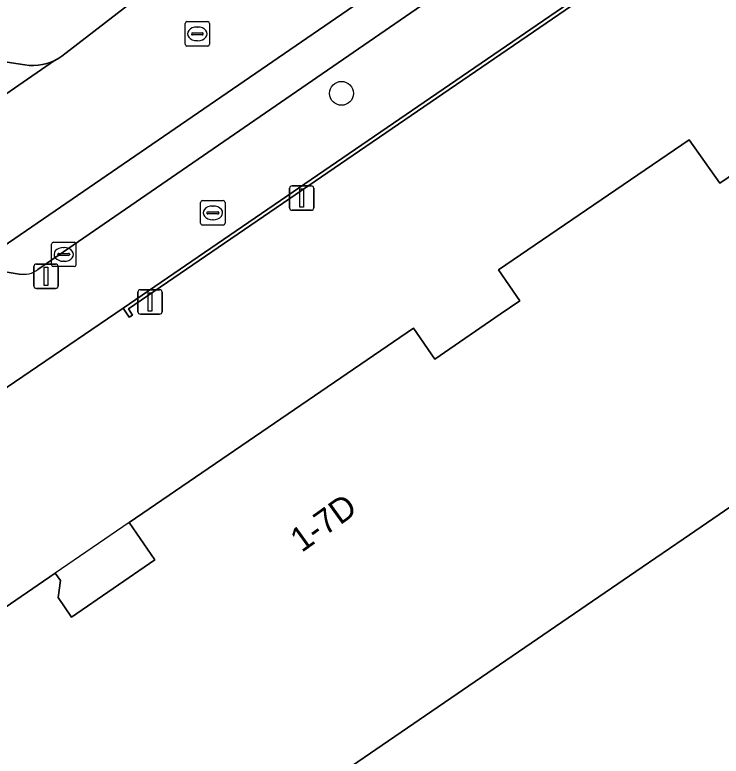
# Model space of a CAD drawing. Extents: x 157445 to 158888, y 383061 to 384688.
# Drawn here: x 158211.1 to 158240.06, y 383581.29 to 383611.7 of the extents above; entities that cross this region are included whole.
import ezdxf

# ---------------------------------------------------------------- set-up
doc = ezdxf.new("R2010")
doc.units = 0
for name, color, linetype in [('IMGEO_Boom', 7, 'Continuous'), ('IMGEO_Brandkraan', 7, 'Continuous'), ('IMGEO_Erf', 7, 'Continuous'), ('IMGEO_Kolk', 7, 'Continuous'), ('IMGEO_Lichtmast', 7, 'Continuous'), ('IMGEO_Muur', 7, 'Continuous'), ('IMGEO_Pand', 7, 'Continuous'), ('IMGEO_Pand_nummerreeks', 7, 'Continuous'), ('IMGEO_Pand_overbouw', 7, 'Continuous'), ('IMGEO_Parkeervlak_open', 7, 'Continuous'), ('IMGEO_Rijbaan_lokaal_open', 7, 'Continuous'), ('IMGEO_Rioolput', 7, 'Continuous'), ('IMGEO_Voetpad_open', 7, 'Continuous')]:
    doc.layers.add(name, color=color, linetype=linetype)

msp = doc.modelspace()

# ---------------------------------------------------------------- linework, layer by layer
at = {"layer": 'IMGEO_Boom'}
msp.add_circle((158224.494, 383608.475), 0.489, dxfattribs=at)
at = {"layer": 'IMGEO_Brandkraan'}
for p, q in [((158218.718, 383603.147), (158218.718, 383603.999)), ((158218.793, 383604.073), (158219.645, 383604.073)), ((158219.719, 383603.999), (158219.719, 383603.147)), ((158218.977, 383603.567), (158218.977, 383603.579)), ((158219.02, 383603.616), (158219.418, 383603.616)), ((158219.206, 383603.853), (158219.231, 383603.853)), ((158219.461, 383603.579), (158219.461, 383603.567)), ((158219.415, 383603.53), (158219.017, 383603.53)), ((158219.229, 383603.293), (158219.204, 383603.293)), ((158219.645, 383603.073), (158218.793, 383603.073))]:
    msp.add_line(p, q, dxfattribs=at)
for points in [[(158218.718, 383603.147), (158218.718, 383603.999)], [(158218.793, 383604.073), (158219.645, 383604.073)], [(158219.719, 383603.999), (158219.719, 383603.147)], [(158219.645, 383603.073), (158218.793, 383603.073)]]:
    msp.add_lwpolyline(points, dxfattribs=at)
for centre, radius, start, end in [((158218.795, 383603.997), 0.0765, 91.552, 178.448), ((158218.795, 383603.997), 0.0765, 91.552, 178.448), ((158219.643, 383603.997), 0.0765, 1.552, 88.448), ((158219.643, 383603.997), 0.0765, 1.552, 88.448), ((158219.017, 383603.576), 0.0403, 85.8775, 175.7526), ((158219.014, 383603.566), 0.0366, 178.938, 274.7102), ((158219.418, 383603.573), 0.043, 264.8664, 352.4533), ((158219.422, 383603.578), 0.0386, 1.7309, 96.639), ((158218.795, 383603.149), 0.0765, 181.552, 268.448), ((158218.795, 383603.149), 0.0765, 181.552, 268.448), ((158219.643, 383603.149), 0.0765, 271.552, 358.448), ((158219.643, 383603.149), 0.0765, 271.552, 358.448)]:
    msp.add_arc(centre, radius, start, end, dxfattribs=at)
for centre, major_axis, ratio, start_param, end_param in [((158219.205, 383603.573), (-0.387, 0.002), 0.722429, 4.712389, 7.853982), ((158219.23, 383603.573), (-0.39, 0.002), 0.717154, 1.570796, 4.712389)]:
    msp.add_ellipse(centre, major_axis=major_axis, ratio=ratio, start_param=start_param, end_param=end_param, dxfattribs=at)
at = {"layer": 'IMGEO_Erf'}
for points in [[(158240.122, 383614.615), (158240.015, 383614.801), (158239.881, 383614.717), (158239.2, 383615.691), (158215.763, 383599.631), (158215.929, 383599.377), (158215.792, 383599.296), (158215.538, 383599.669), (158207.907, 383594.462), (158208.164, 383594.074), (158208.035, 383593.982), (158207.86, 383594.239), (158192.558, 383583.752), (158193.231, 383582.756), (158193.094, 383582.665), (158193.198, 383582.481), (158193.29, 383582.542), (158193.385, 383582.412), (158192.146, 383581.575), (158209.881, 383555.629)], [(158200.748, 383580.567), (158212.758, 383588.789), (158212.978, 383588.491), (158212.869, 383587.792), (158213.429, 383586.988), (158216.843, 383589.337), (158215.793, 383590.872), (158227.446, 383598.845), (158228.316, 383597.574), (158231.001, 383599.411), (158231.8, 383599.958), (158230.932, 383601.23), (158238.75, 383606.566), (158240, 383604.79), (158243.968, 383607.489), (158249.07, 383600.072), (158246.747, 383598.511), (158248.015, 383596.714), (158238.501, 383590.195), (158236.822, 383589.045), (158223.385, 383579.839)]]:
    msp.add_lwpolyline(points, dxfattribs=at)
at = {"layer": 'IMGEO_Kolk'}
for p, q in [((158212.681, 383602.367), (158213.533, 383602.367)), ((158212.606, 383601.441), (158212.606, 383602.293)), ((158213.094, 383602.147), (158213.119, 383602.147)), ((158213.607, 383602.293), (158213.607, 383601.441)), ((158212.865, 383601.861), (158212.865, 383601.873)), ((158213.303, 383601.824), (158212.905, 383601.824)), ((158212.908, 383601.91), (158213.306, 383601.91)), ((158213.349, 383601.873), (158213.349, 383601.861)), ((158213.117, 383601.587), (158213.092, 383601.587)), ((158213.533, 383601.367), (158212.681, 383601.367))]:
    msp.add_line(p, q, dxfattribs=at)
for points in [[(158212.681, 383602.367), (158213.533, 383602.367)], [(158212.606, 383601.441), (158212.606, 383602.293)], [(158213.607, 383602.293), (158213.607, 383601.441)], [(158213.533, 383601.367), (158212.681, 383601.367)]]:
    msp.add_lwpolyline(points, dxfattribs=at)
for centre, radius, start, end in [((158212.683, 383602.291), 0.0765, 91.552, 178.448), ((158212.683, 383602.291), 0.0765, 91.552, 178.448), ((158213.531, 383602.291), 0.0765, 1.552, 88.448), ((158213.531, 383602.291), 0.0765, 1.552, 88.448), ((158212.905, 383601.87), 0.0403, 85.8775, 175.7526), ((158212.902, 383601.86), 0.0366, 178.938, 274.7102), ((158213.306, 383601.867), 0.043, 264.8664, 352.4533), ((158213.31, 383601.872), 0.0386, 1.7309, 96.639), ((158212.683, 383601.443), 0.0765, 181.552, 268.448), ((158212.683, 383601.443), 0.0765, 181.552, 268.448), ((158213.531, 383601.443), 0.0765, 271.552, 358.448), ((158213.531, 383601.443), 0.0765, 271.552, 358.448)]:
    msp.add_arc(centre, radius, start, end, dxfattribs=at)
for centre, major_axis, ratio, start_param, end_param in [((158213.093, 383601.867), (-0.387, 0.002), 0.722429, 4.712389, 7.853982), ((158213.118, 383601.867), (-0.39, 0.002), 0.717154, 1.570796, 4.712389)]:
    msp.add_ellipse(centre, major_axis=major_axis, ratio=ratio, start_param=start_param, end_param=end_param, dxfattribs=at)
at = {"layer": 'IMGEO_Lichtmast'}
for p, q in [((158222.365, 383603.78), (158222.365, 383604.58)), ((158222.365, 383604.58), (158222.365, 383603.78)), ((158222.465, 383604.68), (158223.255, 383604.68)), ((158223.255, 383604.68), (158222.465, 383604.68)), ((158223.355, 383604.58), (158223.355, 383603.78)), ((158223.355, 383603.78), (158223.355, 383604.58)), ((158223.255, 383603.68), (158222.465, 383603.68)), ((158222.465, 383603.68), (158223.255, 383603.68)), ((158211.982, 383601.472), (158212.772, 383601.472)), ((158212.772, 383601.472), (158211.982, 383601.472)), ((158211.882, 383600.572), (158211.882, 383601.372)), ((158211.882, 383601.372), (158211.882, 383600.572)), ((158212.872, 383601.372), (158212.872, 383600.572)), ((158212.872, 383600.572), (158212.872, 383601.372)), ((158212.772, 383600.472), (158211.982, 383600.472)), ((158211.982, 383600.472), (158212.772, 383600.472)), ((158216.146, 383599.518), (158216.146, 383600.318)), ((158216.146, 383600.318), (158216.146, 383599.518)), ((158216.246, 383600.418), (158217.036, 383600.418)), ((158217.036, 383600.418), (158216.246, 383600.418)), ((158217.136, 383600.318), (158217.136, 383599.518)), ((158217.136, 383599.518), (158217.136, 383600.318)), ((158217.036, 383599.418), (158216.246, 383599.418)), ((158216.246, 383599.418), (158217.036, 383599.418))]:
    msp.add_line(p, q, dxfattribs=at)
for points in [[(158222.785, 383604.555), (158222.935, 383604.555), (158222.935, 383603.805), (158222.785, 383603.805), (158222.785, 383604.555)], [(158212.302, 383601.347), (158212.452, 383601.347), (158212.452, 383600.597), (158212.302, 383600.597), (158212.302, 383601.347)], [(158216.566, 383600.293), (158216.716, 383600.293), (158216.716, 383599.543), (158216.566, 383599.543), (158216.566, 383600.293)]]:
    msp.add_lwpolyline(points, dxfattribs=at)
for centre, start, end in [((158222.465, 383604.58), 90, 180), ((158222.465, 383604.58), 90, 180), ((158223.255, 383604.58), 0, 90), ((158223.255, 383604.58), 360, 90), ((158222.465, 383603.78), 180, 270), ((158222.465, 383603.78), 180, 270), ((158223.255, 383603.78), 270, 0), ((158223.255, 383603.78), 270, 0), ((158211.982, 383601.372), 90, 180), ((158211.982, 383601.372), 90, 180), ((158212.772, 383601.372), 0, 90), ((158212.772, 383601.372), 360, 90), ((158211.982, 383600.572), 180, 270), ((158211.982, 383600.572), 180, 270), ((158212.772, 383600.572), 270, 0), ((158212.772, 383600.572), 270, 0), ((158216.246, 383600.318), 90, 180), ((158216.246, 383600.318), 90, 180), ((158217.036, 383600.318), 0, 90), ((158217.036, 383600.318), 360, 90), ((158216.246, 383599.518), 180, 270), ((158216.246, 383599.518), 180, 270), ((158217.036, 383599.518), 270, 0), ((158217.036, 383599.518), 270, 0)]:
    msp.add_arc(centre, 0.1, start, end, dxfattribs=at)
at = {"layer": 'IMGEO_Muur'}
msp.add_lwpolyline([(158239.233, 383615.894), (158215.538, 383599.669), (158215.792, 383599.296), (158215.929, 383599.377), (158215.763, 383599.631), (158239.2, 383615.691), (158239.881, 383614.717), (158240.015, 383614.801)], close=True, dxfattribs=at)
at = {"layer": 'IMGEO_Pand'}
msp.add_lwpolyline([(158223.385, 383579.839), (158236.822, 383589.045), (158238.501, 383590.195), (158248.015, 383596.714), (158246.747, 383598.511), (158249.07, 383600.072), (158243.968, 383607.489), (158240, 383604.79), (158238.75, 383606.566), (158230.932, 383601.23), (158231.8, 383599.958), (158231.001, 383599.411), (158228.316, 383597.574), (158227.446, 383598.845), (158215.793, 383590.872), (158216.843, 383589.337), (158213.429, 383586.988), (158212.869, 383587.792), (158212.978, 383588.491), (158212.758, 383588.789), (158200.748, 383580.567)], dxfattribs=at)
at = {"layer": 'IMGEO_Pand_overbouw'}
msp.add_lwpolyline([(158212.758, 383588.789), (158212.978, 383588.491), (158212.869, 383587.792), (158213.429, 383586.988), (158216.843, 383589.337), (158215.793, 383590.872)], close=True, dxfattribs=at)
at = {"layer": 'IMGEO_Parkeervlak_open'}
for points in [[(158237.43, 383620.603), (158188.489, 383587.021)], [(158212.044, 383601.243), (158212.437, 383601.52), (158231.371, 383614.567)], [(158172.026, 383581.665), (158212.721, 383609.818), (158212.577, 383609.754), (158212.405, 383609.695), (158212.229, 383609.652), (158212.049, 383609.625), (158211.867, 383609.614), (158211.686, 383609.619), (158211.505, 383609.641), (158210.509, 383609.79)], [(158210.297, 383601.22), (158211.28, 383601.064)]]:
    msp.add_lwpolyline(points, dxfattribs=at)
msp.add_arc((158211.447, 383602.073), 1.022, 260.6209, 305.7514, dxfattribs=at)
at = {"layer": 'IMGEO_Rijbaan_lokaal_open'}
msp.add_lwpolyline([(158237.43, 383620.603), (158234.147, 383625.328), (158231.951, 383623.767), (158221.121, 383616.287), (158220.994, 383616.167), (158220.784, 383615.999), (158213.207, 383610.143), (158213.02, 383609.994), (158212.903, 383609.916), (158212.744, 383609.828), (158212.721, 383609.818), (158172.026, 383581.665), (158171.879, 383581.534), (158171.721, 383581.416), (158174.425, 383577.495), (158178.018, 383579.96), (158179.317, 383580.832), (158188.368, 383586.938), (158188.489, 383587.021)], close=True, dxfattribs=at)
at = {"layer": 'IMGEO_Rioolput'}
for p, q in [((158218.082, 383610.489), (158218.082, 383611.341)), ((158218.157, 383611.415), (158219.009, 383611.415)), ((158218.57, 383611.195), (158218.595, 383611.195)), ((158219.083, 383611.341), (158219.083, 383610.489)), ((158218.341, 383610.909), (158218.341, 383610.921)), ((158218.779, 383610.872), (158218.381, 383610.872)), ((158218.384, 383610.958), (158218.782, 383610.958)), ((158218.825, 383610.921), (158218.825, 383610.909)), ((158218.593, 383610.635), (158218.568, 383610.635)), ((158219.009, 383610.415), (158218.157, 383610.415))]:
    msp.add_line(p, q, dxfattribs=at)
for points in [[(158218.082, 383610.489), (158218.082, 383611.341)], [(158218.157, 383611.415), (158219.009, 383611.415)], [(158219.083, 383611.341), (158219.083, 383610.489)], [(158219.009, 383610.415), (158218.157, 383610.415)]]:
    msp.add_lwpolyline(points, dxfattribs=at)
for centre, radius, start, end in [((158218.159, 383611.339), 0.0765, 91.552, 178.448), ((158218.159, 383611.339), 0.0765, 91.552, 178.448), ((158219.007, 383611.339), 0.0765, 1.552, 88.448), ((158219.007, 383611.339), 0.0765, 1.552, 88.448), ((158218.381, 383610.918), 0.0403, 85.8775, 175.7526), ((158218.378, 383610.908), 0.0366, 178.938, 274.7102), ((158218.782, 383610.915), 0.043, 264.8664, 352.4533), ((158218.786, 383610.92), 0.0386, 1.7309, 96.639), ((158218.159, 383610.491), 0.0765, 181.552, 268.448), ((158218.159, 383610.491), 0.0765, 181.552, 268.448), ((158219.007, 383610.491), 0.0765, 271.552, 358.448), ((158219.007, 383610.491), 0.0765, 271.552, 358.448)]:
    msp.add_arc(centre, radius, start, end, dxfattribs=at)
for centre, major_axis, ratio, start_param, end_param in [((158218.569, 383610.915), (-0.387, 0.002), 0.722429, 4.712389, 7.853982), ((158218.594, 383610.915), (-0.39, 0.002), 0.717154, 1.570796, 4.712389)]:
    msp.add_ellipse(centre, major_axis=major_axis, ratio=ratio, start_param=start_param, end_param=end_param, dxfattribs=at)
at = {"layer": 'IMGEO_Voetpad_open'}
for points in [[(158235.898, 383617.681), (158231.371, 383614.567), (158212.437, 383601.52), (158212.044, 383601.243)], [(158188.489, 383587.021), (158188.368, 383586.938), (158188.974, 383586.056), (158188.059, 383580.776), (158192.324, 383583.788), (158207.907, 383594.462), (158215.538, 383599.669), (158239.233, 383615.894)], [(158210.509, 383609.79), (158211.505, 383609.641), (158211.686, 383609.619), (158211.867, 383609.614), (158212.049, 383609.625), (158212.229, 383609.652), (158212.405, 383609.695), (158212.577, 383609.754), (158212.721, 383609.818), (158212.744, 383609.828), (158212.903, 383609.916), (158213.02, 383609.994), (158213.207, 383610.143), (158220.784, 383615.999)], [(158211.28, 383601.064), (158210.297, 383601.22)]]:
    msp.add_lwpolyline(points, dxfattribs=at)
msp.add_arc((158211.447, 383602.073), 1.022, 260.6209, 305.7514, dxfattribs=at)

# ---------------------------------------------------------------- texts
at = {"layer": 'IMGEO_Pand_nummerreeks'}
msp.add_text('1-7D', height=1, rotation=35.6763, dxfattribs=at).set_placement((158222.859, 383589.618))

doc.saveas('drawing.dxf')
